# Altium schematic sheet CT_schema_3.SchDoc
size 199 x 169 mm
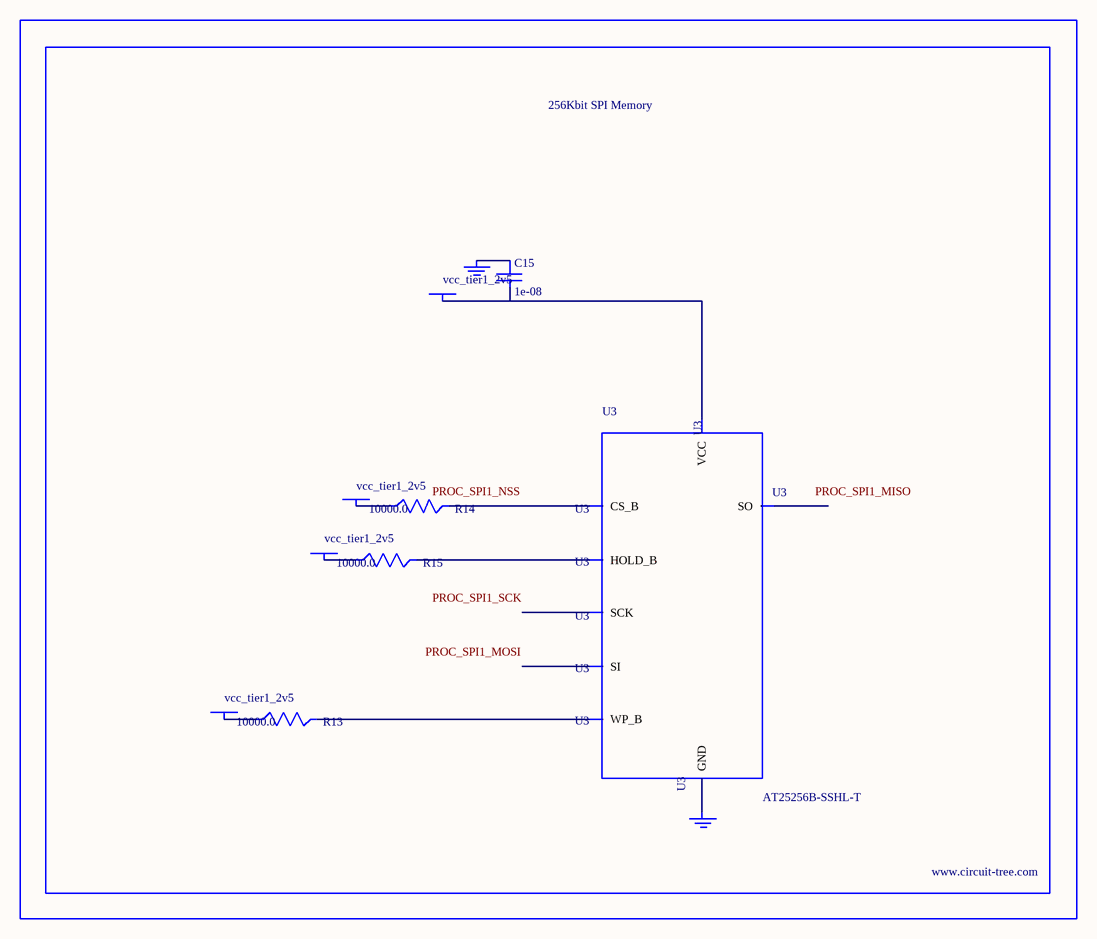
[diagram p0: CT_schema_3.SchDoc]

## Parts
BORDER2  (no value)
C15  1e-08  [C0402]
GND_INSTANCE_2_0  (no value)
GND_INSTANCE_2_1  (no value)
POWER_INSTANCE_2_0  vcc_tier1_2v5
POWER_INSTANCE_2_1  vcc_tier1_2v5
POWER_INSTANCE_2_2  vcc_tier1_2v5
POWER_INSTANCE_2_3  vcc_tier1_2v5
R13  10000.0  [R0603]
R14  10000.0  [R0603]
R15  10000.0  [R0603]
U3  AT25256B-SSHL-T  [SOIC-8]

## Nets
NetC15_1: C15.1 GND_INSTANCE_2_0.0(GND)
NetC15_2: C15.2 POWER_INSTANCE_2_3.0(PWR) U3.8(VCC)
NetGND_INSTANCE_2_1_0: GND_INSTANCE_2_1.0(GND) U3.4(GND)
NetPOWER_INSTANCE_2_0_0: POWER_INSTANCE_2_0.0(PWR) R14.1
NetPOWER_INSTANCE_2_1_0: POWER_INSTANCE_2_1.0(PWR) R13.1
NetPOWER_INSTANCE_2_2_0: POWER_INSTANCE_2_2.0(PWR) R15.1
NetR13_2: R13.2 U3.3(WP_B)
NetR14_2: R14.2 U3.1(CS_B)
NetR15_2: R15.2 U3.7(HOLD_B)

Not connected (* = marked no-connect by the designer): U3 2(SO) 5(SI) 6(SCK)

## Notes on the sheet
- Labels drawn without touching a wire or pin: PROC_SPI1_MISO, PROC_SPI1_MOSI, PROC_SPI1_NSS, PROC_SPI1_SCK

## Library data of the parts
BORDER2 = BORDER_PAGE2
C15 = C0402C103K3RAC
GND_INSTANCE_2_0 GND_INSTANCE_2_1 = GND
POWER_INSTANCE_2_0-POWER_INSTANCE_2_3 = PWR
R13-R15 = RC0603JR-0710KL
